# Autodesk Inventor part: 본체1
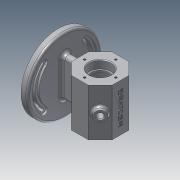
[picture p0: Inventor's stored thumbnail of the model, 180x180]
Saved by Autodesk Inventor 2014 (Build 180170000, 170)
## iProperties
Created: 2017-06
Part Number: 본체1
Material: 알루미늄 6061
Document SubType Name: Modeling
Designer: Administrator
Mass: 555.974 g
Surface Area: 564.009 cm^2
Volume: 205.157 cm^3
Density: 2.71 g/cm^3
Appearance: 알루미늄 - 평지
Author: Administrator
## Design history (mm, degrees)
sketch "스케치1"
  geometry: L1 (12.426, 30)-(30, 12.426); L2 (30, 12.426)-(30, -12.426); L3 (30, -12.426)-(12.426, -30); L4 (12.426, -30)-(-12.426, -30); L5 (-12.426, -30)-(-30, -12.426); L6 (-30, -12.426)-(-30, 12.426); L7 (-30, 12.426)-(-12.426, 30); L8 (-12.426, 30)-(12.426, 30); A1 r 30 centre (0, 0) between (0, 30) and (0, -30); 3 further points
  constraints: 16 end point, 4 midpoint, 4 point on circle, 4 tangent, 1 centre point, 1 coincident
  dimensions: "d0" = 60 diameter of A1
extrude "돌출1" new body sketch "스케치1" stored distance "d1" = 70; taper "d2" = 0 deg
node "작업 평면1"
sketch "스케치3"
  geometry: L1 (0, 24.853)-(0, 42.426) reference; L2 (0, 42.426)-(70, 42.426) reference; 2 further points
  constraints: 1 other
  dimensions: "d4" = 35 distance from line of L1 point (35, 12.426); "d5" = 30 distance from line of L2 point (35, 12.426)
feature "엠보싱1" sketch "스케치3" dims "d6" = 0.5, "d7" = 0
sketch "스케치4"
  geometry: C1 r 8 at (12.426, 35); 1 further point
  constraints: 1 centre point, 1 coincident
  dimensions: "d8" = 16 diameter of C1
extrude "돌출2" join sketch "스케치4" distance "d9" = 7; taper "d10" = 0 deg
node "작업 평면2"
sketch "스케치6"
  geometry: C1 r 55 at (0, 0); 1 further point
  constraints: 1 centre point, 1 coincident
  dimensions: "d12" = 110 diameter of C1
extrude "돌출3" join sketch "스케치6" distance "d13" = 10; taper "d14" = 0 deg
sketch "스케치7"
  geometry: L1 (17.688, 29)-(52, 29); L2 (52, 29)-(52, -29); L3 (52, -29)-(17.688, -29); L4 (17.688, -29)-(17.688, 29); L5 (52, 55)-(52, -55) reference; 3 further points
  constraints: 8 end point, 2 coincident, 2 midpoint, 2 parallel, 1 horizontal, 1 perpendicular
  dimensions: "d15" = 58 distance between parallel lines of L3 L1
extrude "돌출4" join sketch "스케치7" stored distance "d16" = 10; taper "d17" = 0 deg
fillet "모깎기1" dims "d18" = 5
fillet "모깎기2" dims "d19" = 5
fillet "모깎기3" dims "d20" = 5
sketch "스케치9"
  geometry: L1 (0, 0)-(30.406, 30.406); L2 (0, 0)-(-30.406, 30.406); L3 (0, 0)-(30.406, -30.406); L4 (0, 0)-(-30.406, -30.406); C1 r 55 at (0, 0) reference; A1 r 43 centre (0, 0) between (30.406, 30.406) and (-30.406, 30.406); A2 r 48 centre (0, 0) between (33.941, 33.941) and (-33.941, 33.941); A3 r 38 centre (0, 0) between (26.87, 26.87) and (-26.87, 26.87); A4 r 5 centre (30.406, 30.406) between (26.87, 26.87) and (33.941, 33.941); A5 r 5 centre (-30.406, 30.406) between (-33.941, 33.941) and (-26.87, 26.87); A6 r 43 centre (0, 0) between (-30.406, -30.406) and (30.406, -30.406); A7 r 48 centre (0, 0) between (-33.941, -33.941) and (33.941, -33.941); A8 r 38 centre (0, 0) between (-26.87, -26.87) and (26.87, -26.87); A9 r 5 centre (-30.406, -30.406) between (-26.87, -26.87) and (-33.941, -33.941); A10 r 5 centre (30.406, -30.406) between (33.941, -33.941) and (26.87, -26.87); 2 further points
  constraints: 22 point on circle, 10 centre point, 8 end point, 8 tangent, 2 coincident, 2 vertical alignment
  dimensions: "d26" = 90 deg angle of L1 L2; "d27" = 90 deg angle of L4 L3; "d29" = 43 radius of A6; "d30" = 38 radius of A3; "d31" = 38 radius of A8; "d73" = 86 diameter of A1
extrude "돌출5" cut sketch "스케치9" distance "d32" = 3; taper "d33" = 0 deg
sketch "스케치10"
  geometry: C1 r 55 at (0, 0) reference; A1 r 5 centre (-30.406, 30.406) between (-33.941, 33.941) and (-26.87, 26.87) reference; A2 r 5 centre (30.406, 30.406) between (26.87, 26.87) and (33.941, 33.941) reference; A3 r 5 centre (30.406, -30.406) between (33.941, -33.941) and (26.87, -26.87) reference; A4 r 5 centre (-30.406, -30.406) between (-26.87, -26.87) and (-33.941, -33.941) reference; A5 r 43 centre (0, 0) between (30.406, 30.406) and (-30.406, 30.406); A6 r 45 centre (0, 0) between (31.82, 31.82) and (-31.82, 31.82); A7 r 41 centre (0, 0) between (28.991, 28.991) and (-28.991, 28.991); A8 r 2 centre (30.406, 30.406) between (28.991, 28.991) and (31.82, 31.82); A9 r 2 centre (-30.406, 30.406) between (-31.82, 31.82) and (-28.991, 28.991); A10 r 43 centre (0, 0) between (-30.406, -30.406) and (30.406, -30.406); A11 r 45 centre (0, 0) between (-31.82, -31.82) and (31.82, -31.82); A12 r 41 centre (0, 0) between (-28.991, -28.991) and (28.991, -28.991); A13 r 2 centre (-30.406, -30.406) between (-28.991, -28.991) and (-31.82, -31.82); A14 r 2 centre (30.406, -30.406) between (31.82, -31.82) and (28.991, -28.991)
  constraints: 20 point on circle, 10 centre point, 8 tangent, 2 coincident
  dimensions: "d34" = 2 radius of A9; "d35" = 2 radius of A13
extrude "돌출6" cut sketch "스케치10" distance "d36" = 10; taper "d37" = 0 deg
sketch "스케치13"
  geometry: L1 (0, -35)-(-16, -35); L2 (-16, -35)-(-16, -23); L3 (-16, -23)-(0, -23); L4 (0, -23)-(0, -35); L5 (0, -23)-(-14, -23); L6 (-14, -23)-(-14, -20); L7 (-14, -20)-(0, -20); L8 (0, -20)-(0, -23); L9 (0, -20)-(-25, -20); L10 (-25, -20)-(-25, 20); L11 (-25, 20)-(0, 20); L12 (0, 20)-(0, -20); L13 (0, 20)-(-14, 20); L14 (-14, 20)-(-14, 23); L15 (-14, 23)-(0, 23); L16 (0, 23)-(0, 20); L17 (0, 23)-(-16, 23); L18 (-16, 23)-(-16, 35); L19 (-16, 35)-(0, 35); L20 (0, 35)-(0, 23); L21 (12.426, 35)-(-12.426, 35) reference; L22 (-12.426, -35)-(12.426, -35) reference; 1 further point
  constraints: 40 end point, 10 parallel, 5 horizontal, 5 perpendicular, 3 midpoint
  dimensions: "d38" = 32 diameter of L2 L4; "d39" = 28 diameter of L6 L8; "d40" = 50 diameter of L10 L12; "d41" = 28 diameter of L14 L16; "d42" = 32 diameter of L18 L20; "d43" = 12 distance between parallel lines of L1 L3; "d44" = 12 distance between parallel lines of L19 L15; "d45" = 40 distance between parallel lines of L13 L9; "d46" = 3 distance between parallel lines of L15 L13
revolve "회전1" sketch "스케치13" stored, may be unused: angle "d47" = 90 deg
chamfer "모따기1" distance "d48" = 1; stored, may be unused: second distance "d49" = 2, angle "d50" = 45 deg
fillet "모깎기4" dims "d51" = 3
fillet "모깎기5" dims "d52" = 0.3
sketch "스케치14" dims "d53" = 46
  geometry: C1 r 17 at (0, 0) reference; 3 further points
  constraints: 2 coincident, 1 horizontal alignment, 2 other
hole "구멍1" sketch "스케치14" at (23, 0) diameter "d54" = 3.242; stored, may be unused: countersink angle "d58" = 90 deg, drill point angle "d60" = 118 deg; dims "d55" = 8, "d56" = 4, "d57" = 2, "d59" = 10
sketch "스케치15"
  geometry: C1 r 8 at (0, 0) reference; C2 r 4 at (0, 0)
  constraints: 1 centre point, 1 coincident
  dimensions: "d64" = 8 diameter of C2
extrude "돌출7" cut sketch "스케치15" stored distance "d65" = 7; taper "d66" = 0 deg
chamfer "모따기2" distance "d67" = 1; stored, may be unused: second distance "d68" = 2, angle "d69" = 45 deg
fillet "모깎기6" dims "d70" = 3
fillet "모깎기7" dims "d71" = 1
fillet "모깎기8" dims "d72" = 3
node "솔리드1"
pattern_circular "원형 패턴1" dims angle "d62" = 360 deg
mirror "대칭1"
other parameters: "d3" = 5.25, "d11" = -62
